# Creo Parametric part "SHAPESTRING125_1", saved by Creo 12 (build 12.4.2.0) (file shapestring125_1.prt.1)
Units: Custom; MM, KILOGRAM, SECS

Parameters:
  PTC_WM_ITERATION = "0"
  PTC_WM_VERSION = "-.0"
  PTC_WM_LIFECYCLE_STATE = "In Work"
  PTC_WM_LIFECYCLE = "MO_CADDocument"
  PTC_WM_CREATED_BY = "Maximilian Roepper (Z0017RMS: MO)"
  PTC_WM_CREATED_ON = "18-Sep-26 11:36:42 AM"
  PTC_WM_MODIFIED_BY = "Maximilian Roepper (Z0017RMS: MO)"
  PTC_WM_MODIFIED_ON = "18-Sep-26 11:36:46 AM"
  PDMLINKNUMBER = "PDM000071455054"
  PTC_WM_NAME = "shapestring125_1.prt"
  PTC_WM_NUMBER = "PDM000071455054"

Other parameters: WEIGHT, WEIGHT_FACTOR, WEIGHT_ADD, _MASS_TEMP, _DIFF_TEMP, MC_ERRORS, SUPPLIER

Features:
  1. coordinate system
  2. datum plane "PRT_YZ"
  3. datum plane "PRT_XY"
  4. datum plane "PRT_XZ"
  5. coordinate system
  6. datum axis
  7. datum axis
  8. datum axis
  9. coordinate system
  10. imported feature
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
Other named items: PRT, SIEMENS_MO, DRW_VIEW_ORG, PRT_X, PRT_Y, PRT_Z, CS0, ROUGH_GROB

Layers: 00_STD_CSYS-KSYS, 01_STD_PLANES-EBENEN, 02_STD_AXES-ACHSEN, 03_STD_CSYS-KSYS, 24_IMPORT_FEAT-IMPORT_KE, INTFCLR

Surfaces: 1 plane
